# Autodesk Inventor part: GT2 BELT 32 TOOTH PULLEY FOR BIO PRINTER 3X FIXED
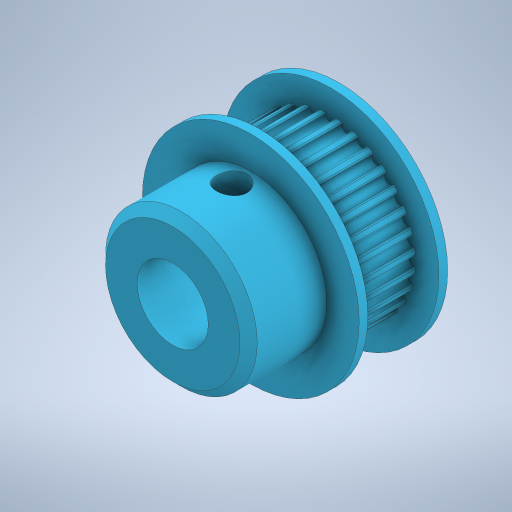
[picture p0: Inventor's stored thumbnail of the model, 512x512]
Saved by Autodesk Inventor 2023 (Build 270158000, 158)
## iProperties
Created: 2025-07
Part Number: GT2 BELT 32 TOOTH PULLEY FOR BIO PRINTER 3X FIXED
Material: Generic
Document SubType Name: Modeling
Designer: erjon
Density: 1 g/cm^3
Appearance: Default
Author: erjon
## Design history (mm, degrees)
feature "Base1"
sketch "Sketch1"
  geometry: 1 further point
sketch "Sketch2"
  geometry: C1 r 10 at (0, 0) reference; C2 r 10 at (0, 0); 1 further point
  constraints: 1 centre point, 1 coincident
extrude "Extrusion1" cut sketch "Sketch2" distance "d0" = 6.2; taper "d1" = 0 deg
sketch "Sketch3" dims "d2" = 19.57
  geometry: L1 (0, 9.785)-(0, 9.035); L2 (0, 9.035)-(0, 9.585); C1 r 4 at (0, 0); A1 r 0.55 centre (0, 9.585) between (-0.517, 9.771) and (0.517, 9.771); A2 r 0.55 centre (-1.87, 9.401) between (-2.414, 9.483) and (-1.399, 9.685); A3 r 0.55 centre (-3.668, 8.855) between (-4.217, 8.829) and (-3.261, 9.226); A4 r 0.55 centre (-5.325, 7.97) between (-5.859, 7.837) and (-4.998, 8.412); A5 r 0.55 centre (-6.778, 6.778) between (-7.275, 6.543) and (-6.543, 7.275); A6 r 0.55 centre (-7.97, 5.325) between (-8.412, 4.998) and (-7.837, 5.859); A7 r 0.55 centre (-8.855, 3.668) between (-9.226, 3.261) and (-8.829, 4.217); A8 r 0.55 centre (-9.401, 1.87) between (-9.685, 1.399) and (-9.483, 2.414); A9 r 0.55 centre (-9.585, 0) between (-9.771, -0.517) and (-9.771, 0.517); A10 r 0.55 centre (-9.401, -1.87) between (-9.483, -2.414) and (-9.685, -1.399); A11 r 0.55 centre (-8.855, -3.668) between (-8.829, -4.217) and (-9.226, -3.261); A12 r 0.55 centre (-7.97, -5.325) between (-7.837, -5.859) and (-8.412, -4.998); A13 r 0.55 centre (-6.778, -6.778) between (-6.543, -7.275) and (-7.275, -6.543); A14 r 0.55 centre (-5.325, -7.97) between (-4.998, -8.412) and (-5.859, -7.837); A15 r 0.55 centre (-3.668, -8.855) between (-3.261, -9.226) and (-4.217, -8.829); A16 r 0.55 centre (-1.87, -9.401) between (-1.399, -9.685) and (-2.414, -9.483); A17 r 0.55 centre (0, -9.585) between (0.517, -9.771) and (-0.517, -9.771); A18 r 0.55 centre (1.87, -9.401) between (2.414, -9.483) and (1.399, -9.685); A19 r 0.55 centre (3.668, -8.855) between (4.217, -8.829) and (3.261, -9.226); A20 r 0.55 centre (5.325, -7.97) between (5.859, -7.837) and (4.998, -8.412); A21 r 0.55 centre (6.778, -6.778) between (7.275, -6.543) and (6.543, -7.275); A22 r 0.55 centre (7.97, -5.325) between (8.412, -4.998) and (7.837, -5.859); A23 r 0.55 centre (8.855, -3.668) between (9.226, -3.261) and (8.829, -4.217); A24 r 0.55 centre (9.401, -1.87) between (9.685, -1.399) and (9.483, -2.414); A25 r 0.55 centre (9.585, 0) between (9.771, 0.517) and (9.771, -0.517); A26 r 0.55 centre (9.401, 1.87) between (9.483, 2.414) and (9.685, 1.399); A27 r 0.55 centre (8.855, 3.668) between (8.829, 4.217) and (9.226, 3.261); A28 r 0.55 centre (7.97, 5.325) between (7.837, 5.859) and (8.412, 4.998); A29 r 0.55 centre (6.778, 6.778) between (6.543, 7.275) and (7.275, 6.543); A30 r 0.55 centre (5.325, 7.97) between (4.998, 8.412) and (5.859, 7.837); A31 r 0.55 centre (3.668, 8.855) between (3.261, 9.226) and (4.217, 8.829); A32 r 0.55 centre (1.87, 9.401) between (1.399, 9.685) and (2.414, 9.483); A33 r 0.15 centre (-0.7, 9.61) between (-0.55, 9.604) and (-0.71, 9.759); A34 r 0.15 centre (-1.189, 9.561) between (-1.207, 9.71) and (-1.335, 9.527); A35 r 0.15 centre (-2.561, 9.288) between (-2.413, 9.313) and (-2.601, 9.433); A36 r 0.15 centre (-3.031, 9.146) between (-3.078, 9.288) and (-3.168, 9.084); A37 r 0.15 centre (-4.324, 8.61) between (-4.183, 8.663) and (-4.391, 8.744); A38 r 0.15 centre (-4.757, 8.379) between (-4.831, 8.509) and (-4.879, 8.291); A39 r 0.15 centre (-5.92, 7.601) between (-5.793, 7.68) and (-6.013, 7.72); A40 r 0.15 centre (-6.3, 7.29) between (-6.398, 7.403) and (-6.403, 7.18); A41 r 0.15 centre (-7.29, 6.3) between (-7.18, 6.403) and (-7.403, 6.398); A42 r 0.15 centre (-7.601, 5.92) between (-7.72, 6.013) and (-7.68, 5.793); A43 r 0.15 centre (-8.379, 4.757) between (-8.291, 4.879) and (-8.509, 4.831); A44 r 0.15 centre (-8.61, 4.324) between (-8.744, 4.391) and (-8.663, 4.183); A45 r 0.15 centre (-9.146, 3.031) between (-9.084, 3.168) and (-9.288, 3.078); A46 r 0.15 centre (-9.288, 2.561) between (-9.433, 2.601) and (-9.313, 2.413); A47 r 0.15 centre (-9.561, 1.189) between (-9.527, 1.335) and (-9.71, 1.207); A48 r 0.15 centre (-9.61, 0.7) between (-9.759, 0.71) and (-9.604, 0.55); A49 r 0.15 centre (-9.61, -0.7) between (-9.604, -0.55) and (-9.759, -0.71); A50 r 0.15 centre (-9.561, -1.189) between (-9.71, -1.207) and (-9.527, -1.335); A51 r 0.15 centre (-9.288, -2.561) between (-9.313, -2.413) and (-9.433, -2.601); A52 r 0.15 centre (-9.146, -3.031) between (-9.288, -3.078) and (-9.084, -3.168); A53 r 0.15 centre (-8.61, -4.324) between (-8.663, -4.183) and (-8.744, -4.391); A54 r 0.15 centre (-8.379, -4.757) between (-8.509, -4.831) and (-8.291, -4.879); A55 r 0.15 centre (-7.601, -5.92) between (-7.68, -5.793) and (-7.72, -6.013); A56 r 0.15 centre (-7.29, -6.3) between (-7.403, -6.398) and (-7.18, -6.403); A57 r 0.15 centre (-6.3, -7.29) between (-6.403, -7.18) and (-6.398, -7.403); A58 r 0.15 centre (-5.92, -7.601) between (-6.013, -7.72) and (-5.793, -7.68); A59 r 0.15 centre (-4.757, -8.379) between (-4.879, -8.291) and (-4.831, -8.509); A60 r 0.15 centre (-4.324, -8.61) between (-4.391, -8.744) and (-4.183, -8.663); A61 r 0.15 centre (-3.031, -9.146) between (-3.168, -9.084) and (-3.078, -9.288); A62 r 0.15 centre (-2.561, -9.288) between (-2.601, -9.433) and (-2.413, -9.313); A63 r 0.15 centre (-1.189, -9.561) between (-1.335, -9.527) and (-1.207, -9.71); A64 r 0.15 centre (-0.7, -9.61) between (-0.71, -9.759) and (-0.55, -9.604)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; 157 further points
  constraints: 226 point on circle, 97 centre point, 4 end point, 3 coincident, 2 tangent, 1 point on line, 1 vertical, 427 other
  dimensions: "d3" = 0.75 distance of L1.start L1.end; "d4" = 0.55 distance of L1.end L2.end; "d7" = 360 deg dimension on point (0, 0) A1.centre (derived); "d9" = 0.3 diameter of A33; "d10" = 0.3 diameter of A34; "d13" = 360 deg dimension on point (0, 0) A33.centre (derived)
extrude "Extrusion2" join sketch "Sketch3" distance "d15" = 6.3; taper "d16" = 0 deg
sketch "Sketch4"
  geometry: C1 r 4 at (0, 0); 1 further point
  constraints: 1 centre point, 1 coincident
extrude "Extrusion3" join sketch "Sketch4" distance "d17" = 17.2; taper "d18" = 0 deg
sketch "Sketch5"
  geometry: L1 (1.533, 2.1)-(-1.533, 2.1); A1 r 2.6 centre (0, 0) between (-1.533, 2.1) and (1.533, 2.1); 1 further point
  constraints: 2 end point, 2 point on circle, 1 centre point, 1 coincident
extrude "Extrusion4" cut sketch "Sketch5" distance "d22" = 17.2; taper "d23" = 0 deg
sketch "Sketch6"
  geometry: C1 r 2.6 at (0, 0); 1 further point
  constraints: 1 centre point, 1 coincident
extrude "Extrusion5" cut sketch "Sketch6" distance "d24" = 4; taper "d25" = 0 deg
sketch "Sketch7"
  geometry: L1 (-2.6, 9)-(2.6, 9) reference; L2 (8.75, 0)-(-8.75, 0) reference; L3 (0, 0)-(0, 2.2); C1 r 1.75 at (0, 2.2)
  constraints: 2 end point, 1 centre point, 1 coincident
  dimensions: "d26" = 2.2 distance of L3.start L3.end; "d27" = 3.5 diameter of C1
extrude "Extrusion6" cut sketch "Sketch7" distance "d28" = 10; taper "d29" = 0 deg
sketch "Sketch8"
  geometry: C1 r 4 at (0, 0); 1 further point
  constraints: 1 centre point, 1 coincident
  dimensions: "d30" = 8 diameter of C1
extrude "Extrusion7" cut sketch "Sketch8" distance "d31" = 50; taper "d32" = 0 deg
sketch "Sketch9"
  geometry: C1 r 12.5 at (0, 0); 1 further point
  constraints: 1 centre point, 1 coincident
extrude "Extrusion8" cut sketch "Sketch9" distance "d33" = 10; taper "d34" = 0 deg
sketch "Sketch10"
  geometry: C1 r 4 at (0, 0) reference; A1 r 9.785 centre (0, 0) between (0.71, -9.759) and (1.207, -9.71) reference; A2 r 0.15 centre (1.189, -9.561) between (1.207, -9.71) and (1.335, -9.527) reference; A3 r 0.55 centre (1.87, -9.401) between (2.413, -9.313) and (1.335, -9.527) reference; A4 r 0.15 centre (2.561, -9.288) between (2.413, -9.313) and (2.601, -9.433) reference; A5 r 9.785 centre (0, 0) between (2.601, -9.433) and (3.078, -9.288) reference; A6 r 0.15 centre (3.031, -9.146) between (3.078, -9.288) and (3.168, -9.084) reference; A7 r 0.55 centre (3.668, -8.855) between (4.183, -8.663) and (3.168, -9.084) reference; A8 r 0.15 centre (4.324, -8.61) between (4.183, -8.663) and (4.391, -8.744) reference; A9 r 9.785 centre (0, 0) between (4.391, -8.744) and (4.831, -8.509) reference; A10 r 0.15 centre (4.757, -8.379) between (4.831, -8.509) and (4.879, -8.291) reference; A11 r 0.55 centre (5.325, -7.97) between (5.793, -7.68) and (4.879, -8.291) reference; A12 r 0.15 centre (5.92, -7.601) between (5.793, -7.68) and (6.013, -7.72) reference; A13 r 9.785 centre (0, 0) between (6.013, -7.72) and (6.398, -7.403) reference; A14 r 0.15 centre (6.3, -7.29) between (6.398, -7.403) and (6.403, -7.18) reference; A15 r 0.55 centre (6.778, -6.778) between (7.18, -6.403) and (6.403, -7.18) reference; A16 r 0.15 centre (7.29, -6.3) between (7.18, -6.403) and (7.403, -6.398) reference; A17 r 9.785 centre (0, 0) between (7.403, -6.398) and (7.72, -6.013) reference; A18 r 0.15 centre (7.601, -5.92) between (7.72, -6.013) and (7.68, -5.793) reference; A19 r 0.55 centre (7.97, -5.325) between (8.291, -4.879) and (7.68, -5.793) reference; A20 r 0.15 centre (8.379, -4.757) between (8.291, -4.879) and (8.509, -4.831) reference; A21 r 9.785 centre (0, 0) between (8.509, -4.831) and (8.744, -4.391) reference; A22 r 0.15 centre (8.61, -4.324) between (8.744, -4.391) and (8.663, -4.183) reference; A23 r 0.55 centre (8.855, -3.668) between (9.084, -3.168) and (8.663, -4.183) reference; A24 r 0.15 centre (9.146, -3.031) between (9.084, -3.168) and (9.288, -3.078) reference; A25 r 9.785 centre (0, 0) between (9.288, -3.078) and (9.433, -2.601) reference; A26 r 0.15 centre (9.288, -2.561) between (9.433, -2.601) and (9.313, -2.413) reference; A27 r 0.55 centre (9.401, -1.87) between (9.527, -1.335) and (9.313, -2.413) reference; A28 r 0.15 centre (9.561, -1.189) between (9.527, -1.335) and (9.71, -1.207) reference; A29 r 9.785 centre (0, 0) between (9.71, -1.207) and (9.759, -0.71) reference; A30 r 0.15 centre (9.61, -0.7) between (9.759, -0.71) and (9.604, -0.55) reference; A31 r 0.55 centre (9.585, 0) between (9.604, 0.55) and (9.604, -0.55) reference; A32 r 0.15 centre (9.61, 0.7) between (9.604, 0.55) and (9.759, 0.71) reference; A33 r 9.785 centre (0, 0) between (9.759, 0.71) and (9.71, 1.207) reference; A34 r 0.15 centre (9.561, 1.189) between (9.71, 1.207) and (9.527, 1.335) reference; A35 r 0.55 centre (9.401, 1.87) between (9.313, 2.413) and (9.527, 1.335) reference; A36 r 0.15 centre (9.288, 2.561) between (9.313, 2.413) and (9.433, 2.601) reference; A37 r 9.785 centre (0, 0) between (9.433, 2.601) and (9.288, 3.078) reference; A38 r 0.15 centre (9.146, 3.031) between (9.288, 3.078) and (9.084, 3.168) reference; A39 r 0.55 centre (8.855, 3.668) between (8.663, 4.183) and (9.084, 3.168) reference; A40 r 0.15 centre (8.61, 4.324) between (8.663, 4.183) and (8.744, 4.391) reference; A41 r 9.785 centre (0, 0) between (8.744, 4.391) and (8.509, 4.831) reference; A42 r 0.15 centre (8.379, 4.757) between (8.509, 4.831) and (8.291, 4.879) reference; A43 r 0.55 centre (7.97, 5.325) between (7.68, 5.793) and (8.291, 4.879) reference; A44 r 0.15 centre (7.601, 5.92) between (7.68, 5.793) and (7.72, 6.013) reference; A45 r 9.785 centre (0, 0) between (7.72, 6.013) and (7.403, 6.398) reference; A46 r 0.15 centre (7.29, 6.3) between (7.403, 6.398) and (7.18, 6.403) reference; A47 r 0.55 centre (6.778, 6.778) between (6.403, 7.18) and (7.18, 6.403) reference; A48 r 0.15 centre (6.3, 7.29) between (6.403, 7.18) and (6.398, 7.403) reference; A49 r 9.785 centre (0, 0) between (6.398, 7.403) and (6.013, 7.72) reference; A50 r 0.15 centre (5.92, 7.601) between (6.013, 7.72) and (5.793, 7.68) reference; A51 r 0.55 centre (5.325, 7.97) between (4.879, 8.291) and (5.793, 7.68) reference; A52 r 0.15 centre (4.757, 8.379) between (4.879, 8.291) and (4.831, 8.509) reference; A53 r 9.785 centre (0, 0) between (4.831, 8.509) and (4.391, 8.744) reference; A54 r 0.15 centre (4.324, 8.61) between (4.391, 8.744) and (4.183, 8.663) reference; A55 r 0.55 centre (3.668, 8.855) between (3.168, 9.084) and (4.183, 8.663) reference; A56 r 0.15 centre (3.031, 9.146) between (3.168, 9.084) and (3.078, 9.288) reference; A57 r 9.785 centre (0, 0) between (3.078, 9.288) and (2.601, 9.433) reference; A58 r 0.15 centre (2.561, 9.288) between (2.601, 9.433) and (2.413, 9.313) reference; A59 r 0.55 centre (1.87, 9.401) between (1.335, 9.527) and (2.413, 9.313) reference; A60 r 0.15 centre (1.189, 9.561) between (1.335, 9.527) and (1.207, 9.71) reference; A61 r 9.785 centre (0, 0) between (1.207, 9.71) and (0.71, 9.759) reference; A62 r 0.15 centre (0.7, 9.61) between (0.71, 9.759) and (0.55, 9.604) reference; A63 r 0.55 centre (0, 9.585) between (-0.55, 9.604) and (0.55, 9.604) reference; A64 r 0.15 centre (-0.7, 9.61) between (-0.55, 9.604) and (-0.71, 9.759) reference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; 1 further point
extrude "Extrusion9" join sketch "Sketch10" distance "d35" = 2; taper "d36" = 0 deg
sketch "Sketch11"
  geometry: C1 r 12.5 at (0, 0); 1 further point
  constraints: 1 centre point, 1 coincident
extrude "Extrusion10" join sketch "Sketch11" distance "d37" = 1; taper "d38" = 0 deg
sketch "Sketch12"
  geometry: C1 r 4.1 at (0, 0); 1 further point
  constraints: 1 centre point, 1 coincident
  dimensions: "d39" = 8.2 diameter of C1
extrude "Extrusion11" cut sketch "Sketch12" distance "d40" = 50; taper "d41" = 0 deg
body "Solid1"
node "Projected Loop1"
